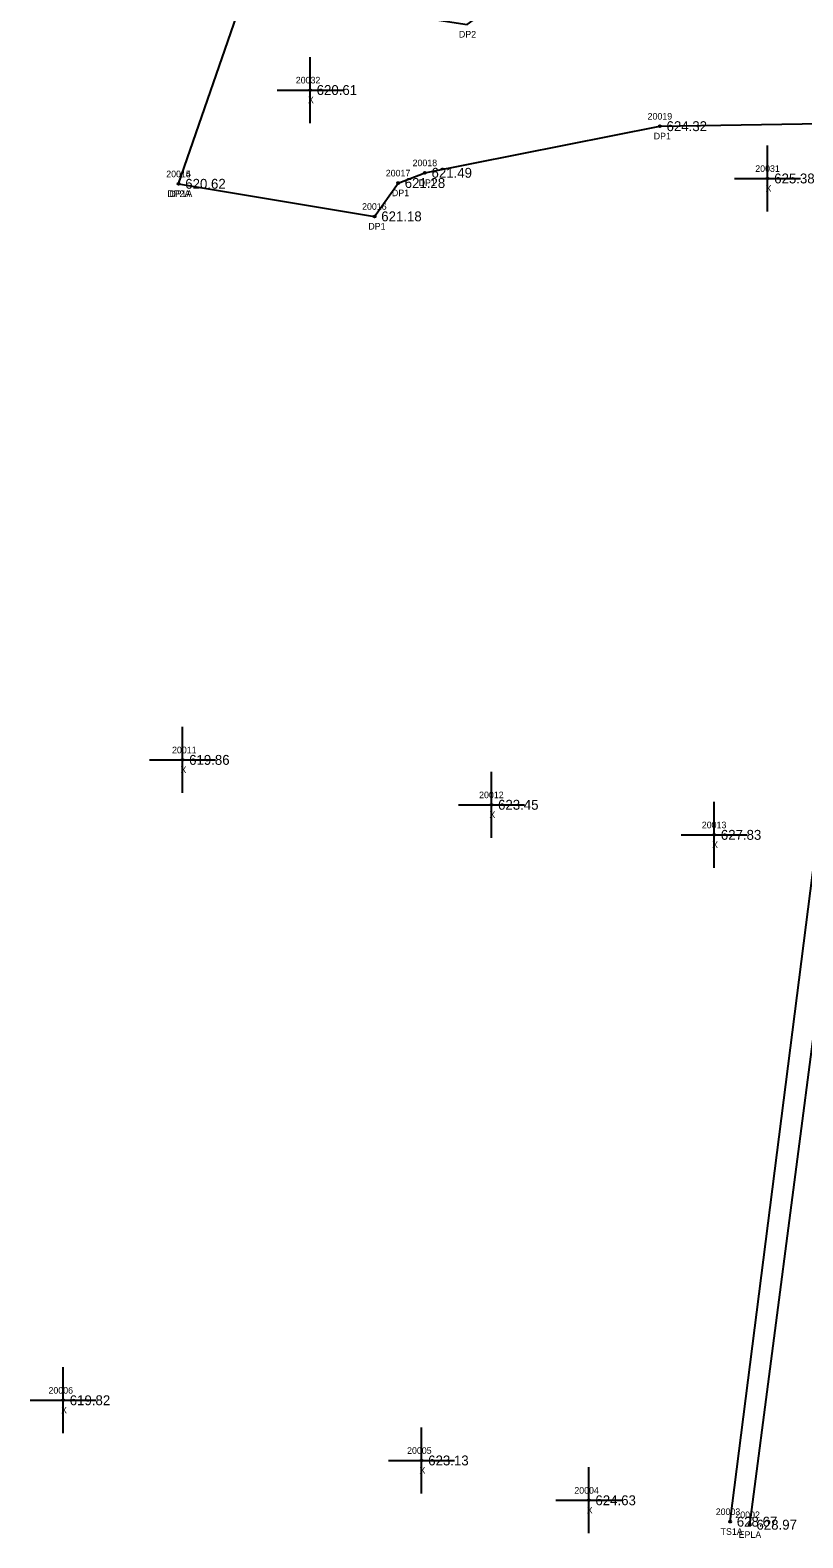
# Model space of a CAD drawing. Extents: x 1695443 to 1696344, y 1087542 to 1090645.
# Drawn here: x 1695749.1 to 1695866.2, y 1087562.9 to 1087791.5 of the extents above; entities that cross this region are included whole.
import ezdxf

# ---------------------------------------------------------------- set-up
doc = ezdxf.new("R2010")
doc.units = 0
for name, color, linetype in [('RD_DTM_BkLn2', 7, 'Continuous'), ('RD_DTM_BkLn_txCode', 7, 'Continuous'), ('RD_EX_Driveway', 7, 'Continuous'), ('RD_EX_Driveway_txCode', 7, 'Continuous'), ('RD_EX_Misc', 7, 'Continuous'), ('RD_EX_Misc_txCode', 7, 'Continuous'), ('RD_EX_Road', 7, 'Continuous'), ('RD_EX_Road_txCode', 7, 'Continuous'), ('RD_EX_TX_Driveway_ELEV', 7, 'Continuous'), ('RD_EX_TX_Misc_ELEV', 7, 'Continuous'), ('RD_EX_TX_Road_ELEV', 7, 'Continuous'), ('RD_SMD_Locator', 7, 'Continuous')]:
    doc.layers.add(name, color=color, linetype=linetype)

msp = doc.modelspace()

# ---------------------------------------------------------------- linework, layer by layer
at = {"layer": 'RD_DTM_BkLn2'}
msp.add_lwpolyline([(1695855.21, 1087565.36), (1695868.41, 1087668.94), (1695881.46, 1087770.8)], dxfattribs=at)
at = {"layer": 'RD_EX_Driveway'}
for points in [[(1695771.6, 1087768.24), (1695781.72, 1087797.59), (1695815.32, 1087792.42), (1695818.05, 1087794.38), (1695818.22, 1087796.57), (1695830.21, 1087795.43), (1695887.48, 1087794.2)], [(1695771.6, 1087768.24), (1695801.31, 1087763.3), (1695804.87, 1087768.36), (1695808.93, 1087769.91), (1695844.56, 1087776.98), (1695878.47, 1087777.52), (1695884.5, 1087774.69)]]:
    msp.add_lwpolyline(points, dxfattribs=at)
at = {"layer": 'RD_EX_Misc'}
for p, q in [((1695791.52, 1087777.46), (1695791.52, 1087787.46)), ((1695786.52, 1087782.46), (1695796.52, 1087782.46)), ((1695860.88, 1087764.05), (1695860.88, 1087774.05)), ((1695855.88, 1087769.05), (1695865.88, 1087769.05)), ((1695772.19, 1087675.88), (1695772.19, 1087685.88)), ((1695767.19, 1087680.88), (1695777.19, 1087680.88)), ((1695819.02, 1087669.07), (1695819.02, 1087679.07)), ((1695852.79, 1087664.51), (1695852.79, 1087674.51)), ((1695814.02, 1087674.07), (1695824.02, 1087674.07)), ((1695847.79, 1087669.51), (1695857.79, 1087669.51)), ((1695754.09, 1087578.77), (1695754.09, 1087588.77)), ((1695749.09, 1087583.77), (1695759.09, 1087583.77)), ((1695808.43, 1087569.64), (1695808.43, 1087579.64)), ((1695803.43, 1087574.64), (1695813.43, 1087574.64)), ((1695833.78, 1087563.6), (1695833.78, 1087573.6)), ((1695828.78, 1087568.6), (1695838.78, 1087568.6))]:
    msp.add_line(p, q, dxfattribs=at)
at = {"layer": 'RD_EX_Road'}
msp.add_lwpolyline([(1695858.19, 1087564.9), (1695871.71, 1087668.82), (1695884.5, 1087774.69), (1695887.48, 1087794.2), (1695897.57, 1087873.43), (1695908.92, 1087975.76), (1695914.49, 1088029.24), (1695917.65, 1088054.8), (1695920.27, 1088079.09), (1695926.98, 1088130.26), (1695934.75, 1088185.09), (1695942.15, 1088234.62), (1695951.36, 1088288.06), (1695961.48, 1088338.41), (1695972.86, 1088394.13), (1695998.53, 1088499.67), (1696024.81, 1088603.86), (1696034.83, 1088656.78)], dxfattribs=at)
at = {"layer": 'RD_SMD_Locator'}
for centre in [(1695791.52, 1087782.46), (1695844.56, 1087776.98), (1695771.6, 1087768.24), (1695771.6, 1087768.24), (1695804.87, 1087768.36), (1695808.93, 1087769.91), (1695860.88, 1087769.05), (1695801.31, 1087763.3), (1695772.19, 1087680.88), (1695819.02, 1087674.07), (1695852.79, 1087669.51), (1695754.09, 1087583.77), (1695808.43, 1087574.64), (1695833.78, 1087568.6), (1695855.21, 1087565.36), (1695858.19, 1087564.9)]:
    msp.add_circle(centre, 0.15, dxfattribs=at)

# ---------------------------------------------------------------- texts
at = {"layer": 'RD_DTM_BkLn_txCode'}
for s, p in [('20003', (1695853.02, 1087566.36)), ('TS1A', (1695853.76, 1087563.36))]:
    msp.add_text(s, height=1, dxfattribs=at).set_placement(p)
at = {"layer": 'RD_EX_Driveway_txCode'}
for s, p in [('DP2', (1695814.09, 1087790.42)), ('20019', (1695842.69, 1087777.98)), ('DP1', (1695843.62, 1087774.98)), ('20017', (1695803, 1087769.36)), ('20018', (1695807.06, 1087770.91)), ('20014', (1695769.72, 1087769.24)), ('20015', (1695769.72, 1087769.24)), ('DP1', (1695807.99, 1087767.91)), ('DP2A', (1695769.88, 1087766.24)), ('DP1A', (1695770.17, 1087766.24)), ('DP1', (1695803.93, 1087766.36)), ('20016', (1695799.41, 1087764.3)), ('DP1', (1695800.36, 1087761.3))]:
    msp.add_text(s, height=1, dxfattribs=at).set_placement(p)
at = {"layer": 'RD_EX_Misc_txCode'}
for s, p in [('20032', (1695789.36, 1087783.46)), ('X', (1695791.2, 1087780.46)), ('20031', (1695859.01, 1087770.05)), ('X', (1695860.57, 1087767.05)), ('20011', (1695770.6, 1087681.88)), ('X', (1695771.88, 1087678.88)), ('20012', (1695817.15, 1087675.07)), ('X', (1695818.71, 1087672.07)), ('20013', (1695850.91, 1087670.51)), ('X', (1695852.47, 1087667.51)), ('20006', (1695751.87, 1087584.77)), ('X', (1695753.78, 1087581.77)), ('20005', (1695806.23, 1087575.64)), ('X', (1695808.11, 1087572.64)), ('20004', (1695831.58, 1087569.6)), ('X', (1695833.46, 1087566.6))]:
    msp.add_text(s, height=1, dxfattribs=at).set_placement(p)
at = {"layer": 'RD_EX_Road_txCode'}
for s, p in [('20002', (1695855.99, 1087565.9)), ('EPLA', (1695856.49, 1087562.9))]:
    msp.add_text(s, height=1, dxfattribs=at).set_placement(p)
at = {"layer": 'RD_EX_TX_Driveway_ELEV'}
for s, p in [('624.32', (1695845.56, 1087776.23)), ('621.49', (1695809.93, 1087769.16)), ('620.62', (1695772.6, 1087767.49)), ('620.62', (1695772.6, 1087767.49)), ('621.28', (1695805.87, 1087767.61)), ('621.18', (1695802.31, 1087762.55))]:
    msp.add_text(s, height=1.5, dxfattribs=at).set_placement(p)
at = {"layer": 'RD_EX_TX_Misc_ELEV'}
for s, p in [('620.61', (1695792.52, 1087781.71)), ('625.38', (1695861.88, 1087768.3)), ('619.86', (1695773.19, 1087680.13)), ('623.45', (1695820.02, 1087673.32)), ('627.83', (1695853.79, 1087668.76)), ('619.82', (1695755.09, 1087583.02)), ('623.13', (1695809.43, 1087573.89)), ('624.63', (1695834.78, 1087567.85)), ('628.67', (1695856.21, 1087564.61))]:
    msp.add_text(s, height=1.5, dxfattribs=at).set_placement(p)
at = {"layer": 'RD_EX_TX_Road_ELEV'}
msp.add_text('628.97', height=1.5, dxfattribs=at).set_placement((1695859.19, 1087564.15))

doc.saveas('drawing.dxf')
